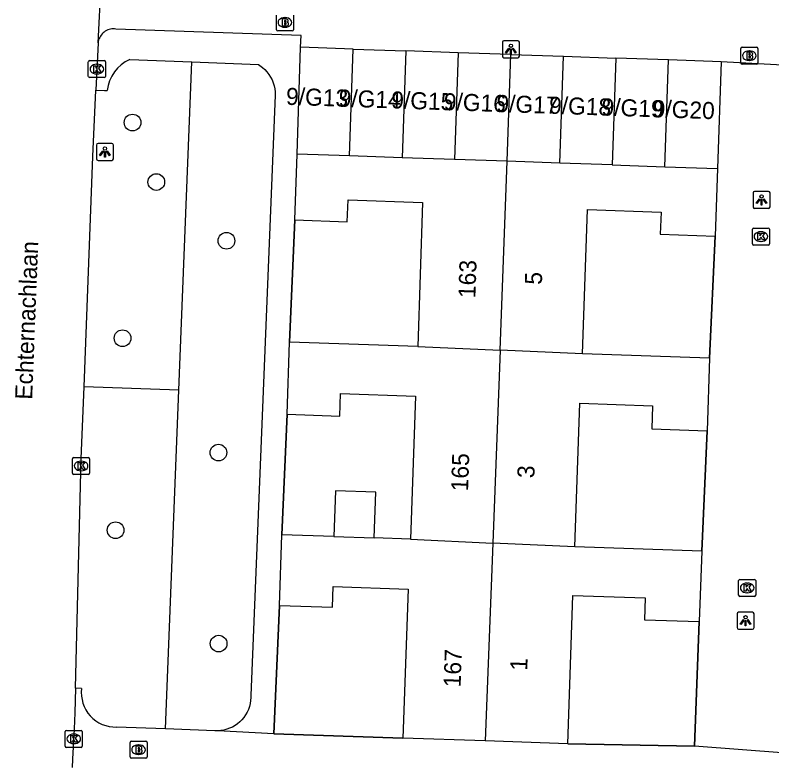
# Model space of a CAD drawing. Extents: x 160787 to 161428, y 386828 to 387483.
# Drawn here: x 160937.91 to 160982.31, y 387304.46 to 387348.48 of the extents above; entities that cross this region are included whole.
import ezdxf

# ---------------------------------------------------------------- set-up
doc = ezdxf.new("R2010")
doc.units = 0
for name, color, linetype in [('IMGEO_Boom', 7, 'Continuous'), ('IMGEO_Brandkraan', 7, 'Continuous'), ('IMGEO_Groenvoorziening', 7, 'Continuous'), ('IMGEO_Kolk', 7, 'Continuous'), ('IMGEO_Lichtpunt', 7, 'Continuous'), ('IMGEO_Muur', 7, 'Continuous'), ('IMGEO_Openbare_ruimte_label', 7, 'Continuous'), ('IMGEO_Pand', 7, 'Continuous'), ('IMGEO_Pand_nummerreeks', 7, 'Continuous'), ('IMGEO_Rijbaan_lokaal_gesloten', 7, 'Continuous'), ('IMGEO_Rijbaan_lokaal_open', 7, 'Continuous'), ('IMGEO_Voetpad_open', 7, 'Continuous')]:
    doc.layers.add(name, color=color, linetype=linetype)

msp = doc.modelspace()

# ---------------------------------------------------------------- linework, layer by layer
at = {"layer": 'IMGEO_Boom'}
for centre in [(160944.795, 387342.186), (160946.193, 387338.697), (160950.31, 387335.252), (160944.21, 387329.535), (160949.837, 387322.826), (160943.805, 387318.279), (160949.851, 387311.625)]:
    msp.add_circle(centre, 0.489, dxfattribs=at)
at = {"layer": 'IMGEO_Brandkraan'}
for p, q in [((160953.239, 387347.631), (160953.239, 387348.483)), ((160954.24, 387348.483), (160954.24, 387347.631)), ((160953.727, 387348.337), (160953.752, 387348.337)), ((160954.166, 387347.557), (160953.314, 387347.557)), ((160953.75, 387347.777), (160953.725, 387347.777)), ((160980.488, 387345.681), (160980.488, 387346.533)), ((160980.563, 387346.607), (160981.415, 387346.607)), ((160980.976, 387346.387), (160981.001, 387346.387)), ((160981.489, 387346.533), (160981.489, 387345.681)), ((160980.999, 387345.827), (160980.974, 387345.827)), ((160981.415, 387345.607), (160980.563, 387345.607)), ((160944.651, 387304.979), (160944.651, 387305.831)), ((160944.726, 387305.905), (160945.578, 387305.905)), ((160945.652, 387305.831), (160945.652, 387304.979)), ((160945.139, 387305.685), (160945.164, 387305.685)), ((160945.578, 387304.905), (160944.726, 387304.905)), ((160945.162, 387305.125), (160945.137, 387305.125))]:
    msp.add_line(p, q, dxfattribs=at)
for points in [[(160953.239, 387347.631), (160953.239, 387348.483)], [(160954.24, 387348.483), (160954.24, 387347.631)], [(160953.587, 387348.257), (160953.587, 387347.857), (160953.8, 387347.857)], [(160953.818, 387348.257), (160953.587, 387348.257)], [(160953.766, 387348.176), (160953.712, 387348.176), (160953.712, 387348.1)], [(160953.712, 387348.1), (160953.765, 387348.1)], [(160953.774, 387348.024), (160953.712, 387348.024), (160953.712, 387347.943)], [(160954.166, 387347.557), (160953.314, 387347.557)], [(160953.712, 387347.943), (160953.774, 387347.943)], [(160980.488, 387345.681), (160980.488, 387346.533)], [(160980.563, 387346.607), (160981.415, 387346.607)], [(160980.836, 387346.307), (160980.836, 387345.907), (160981.049, 387345.907)], [(160981.067, 387346.307), (160980.836, 387346.307)], [(160981.015, 387346.226), (160980.961, 387346.226), (160980.961, 387346.15)], [(160981.489, 387346.533), (160981.489, 387345.681)], [(160980.961, 387346.15), (160981.014, 387346.15)], [(160981.023, 387346.074), (160980.961, 387346.074), (160980.961, 387345.993)], [(160980.961, 387345.993), (160981.023, 387345.993)], [(160981.415, 387345.607), (160980.563, 387345.607)], [(160944.651, 387304.979), (160944.651, 387305.831)], [(160944.726, 387305.905), (160945.578, 387305.905)], [(160945.652, 387305.831), (160945.652, 387304.979)], [(160944.999, 387305.605), (160944.999, 387305.205), (160945.212, 387305.205)], [(160945.23, 387305.605), (160944.999, 387305.605)], [(160945.178, 387305.524), (160945.124, 387305.524), (160945.124, 387305.448)], [(160945.124, 387305.448), (160945.177, 387305.448)], [(160945.186, 387305.372), (160945.124, 387305.372), (160945.124, 387305.291)], [(160945.578, 387304.905), (160944.726, 387304.905)], [(160945.124, 387305.291), (160945.186, 387305.291)]]:
    msp.add_lwpolyline(points, dxfattribs=at)
for centre, radius, start, end in [((160953.767, 387348.138), 0.0379, 267.8285, 90.9355), ((160953.775, 387347.983), 0.0404, 269.8759, 90.5077), ((160953.822, 387348.112), 0.145, 59.4692, 91.5367), ((160953.847, 387348.159), 0.0922, 285.5137, 58.1501), ((160953.852, 387347.967), 0.105, 301.3115, 78.989), ((160953.316, 387347.633), 0.0765, 181.552, 268.448), ((160953.316, 387347.633), 0.0765, 181.552, 268.448), ((160953.806, 387348.108), 0.251, 268.6676, 293.5347), ((160954.164, 387347.633), 0.0765, 271.552, 358.448), ((160954.164, 387347.633), 0.0765, 271.552, 358.448), ((160980.565, 387346.531), 0.0765, 91.552, 178.448), ((160980.565, 387346.531), 0.0765, 91.552, 178.448), ((160981.016, 387346.188), 0.0379, 267.8285, 90.9355), ((160981.071, 387346.162), 0.145, 59.4692, 91.5367), ((160981.096, 387346.209), 0.0922, 285.5137, 58.1501), ((160981.413, 387346.531), 0.0765, 1.552, 88.448), ((160981.413, 387346.531), 0.0765, 1.552, 88.448), ((160981.024, 387346.033), 0.0404, 269.8759, 90.5077), ((160981.055, 387346.158), 0.251, 268.6676, 293.5347), ((160981.101, 387346.017), 0.105, 301.3115, 78.989), ((160980.565, 387345.683), 0.0765, 181.552, 268.448), ((160980.565, 387345.683), 0.0765, 181.552, 268.448), ((160981.413, 387345.683), 0.0765, 271.552, 358.448), ((160981.413, 387345.683), 0.0765, 271.552, 358.448), ((160944.728, 387305.829), 0.0765, 91.552, 178.448), ((160944.728, 387305.829), 0.0765, 91.552, 178.448), ((160945.576, 387305.829), 0.0765, 1.552, 88.448), ((160945.576, 387305.829), 0.0765, 1.552, 88.448), ((160945.179, 387305.486), 0.0379, 267.8285, 90.9355), ((160945.187, 387305.331), 0.0404, 269.8759, 90.5077), ((160945.234, 387305.46), 0.145, 59.4692, 91.5367), ((160945.259, 387305.507), 0.0922, 285.5137, 58.1501), ((160945.264, 387305.315), 0.105, 301.3115, 78.989), ((160944.728, 387304.981), 0.0765, 181.552, 268.448), ((160944.728, 387304.981), 0.0765, 181.552, 268.448), ((160945.218, 387305.456), 0.251, 268.6676, 293.5347), ((160945.576, 387304.981), 0.0765, 271.552, 358.448), ((160945.576, 387304.981), 0.0765, 271.552, 358.448)]:
    msp.add_arc(centre, radius, start, end, dxfattribs=at)
for centre, major_axis, ratio, start_param, end_param in [((160953.726, 387348.057), (-0.387, 0.002), 0.722429, 4.712389, 7.853982), ((160953.751, 387348.057), (-0.39, 0.002), 0.717154, 1.570796, 4.712389), ((160980.975, 387346.107), (-0.387, 0.002), 0.722429, 4.712389, 7.853982), ((160981, 387346.107), (-0.39, 0.002), 0.717154, 1.570796, 4.712389), ((160945.138, 387305.405), (-0.387, 0.002), 0.722429, 4.712389, 7.853982), ((160945.163, 387305.405), (-0.39, 0.002), 0.717154, 1.570796, 4.712389)]:
    msp.add_ellipse(centre, major_axis=major_axis, ratio=ratio, start_param=start_param, end_param=end_param, dxfattribs=at)
at = {"layer": 'IMGEO_Groenvoorziening'}
for points in [[(160947.517, 387326.494), (160948.269, 387345.743)], [(160947.517, 387326.494), (160941.952, 387326.681)], [(160946.741, 387306.626), (160947.517, 387326.494)]]:
    msp.add_lwpolyline(points, dxfattribs=at)
at = {"layer": 'IMGEO_Kolk'}
for p, q in [((160942.278, 387345.82), (160943.13, 387345.82)), ((160942.203, 387344.894), (160942.203, 387345.746)), ((160942.691, 387345.6), (160942.716, 387345.6)), ((160943.204, 387345.746), (160943.204, 387344.894)), ((160942.714, 387345.04), (160942.689, 387345.04)), ((160943.13, 387344.82), (160942.278, 387344.82)), ((160981.244, 387335.997), (160982.096, 387335.997)), ((160981.169, 387335.071), (160981.169, 387335.923)), ((160981.657, 387335.777), (160981.682, 387335.777)), ((160982.17, 387335.923), (160982.17, 387335.071)), ((160981.68, 387335.217), (160981.655, 387335.217)), ((160982.096, 387334.997), (160981.244, 387334.997)), ((160941.278, 387321.619), (160941.278, 387322.471)), ((160941.353, 387322.545), (160942.205, 387322.545)), ((160941.766, 387322.325), (160941.791, 387322.325)), ((160942.279, 387322.471), (160942.279, 387321.619)), ((160942.205, 387321.545), (160941.353, 387321.545)), ((160941.789, 387321.765), (160941.764, 387321.765)), ((160980.364, 387314.467), (160980.364, 387315.319)), ((160980.439, 387315.393), (160981.291, 387315.393)), ((160980.852, 387315.173), (160980.877, 387315.173)), ((160981.365, 387315.319), (160981.365, 387314.467)), ((160981.291, 387314.393), (160980.439, 387314.393)), ((160980.875, 387314.613), (160980.85, 387314.613)), ((160940.846, 387305.614), (160940.846, 387306.466)), ((160940.921, 387306.54), (160941.773, 387306.54)), ((160941.334, 387306.32), (160941.359, 387306.32)), ((160941.847, 387306.466), (160941.847, 387305.614)), ((160941.773, 387305.54), (160940.921, 387305.54)), ((160941.357, 387305.76), (160941.332, 387305.76))]:
    msp.add_line(p, q, dxfattribs=at)
for points in [[(160942.278, 387345.82), (160943.13, 387345.82)], [(160942.203, 387344.894), (160942.203, 387345.746)], [(160942.524, 387345.52), (160942.647, 387345.52), (160942.647, 387345.369), (160942.777, 387345.52), (160942.941, 387345.52), (160942.795, 387345.369), (160942.948, 387345.12), (160942.796, 387345.12), (160942.711, 387345.284), (160942.647, 387345.217), (160942.647, 387345.12), (160942.524, 387345.12), (160942.524, 387345.52)], [(160943.204, 387345.746), (160943.204, 387344.894)], [(160943.13, 387344.82), (160942.278, 387344.82)], [(160981.244, 387335.997), (160982.096, 387335.997)], [(160981.169, 387335.071), (160981.169, 387335.923)], [(160981.49, 387335.697), (160981.613, 387335.697), (160981.613, 387335.546), (160981.743, 387335.697), (160981.907, 387335.697), (160981.761, 387335.546), (160981.914, 387335.297), (160981.762, 387335.297), (160981.677, 387335.461), (160981.613, 387335.394), (160981.613, 387335.297), (160981.49, 387335.297), (160981.49, 387335.697)], [(160982.17, 387335.923), (160982.17, 387335.071)], [(160982.096, 387334.997), (160981.244, 387334.997)], [(160941.278, 387321.619), (160941.278, 387322.471)], [(160941.353, 387322.545), (160942.205, 387322.545)], [(160941.599, 387322.245), (160941.722, 387322.245), (160941.722, 387322.094), (160941.852, 387322.245), (160942.016, 387322.245), (160941.87, 387322.094), (160942.023, 387321.845), (160941.871, 387321.845), (160941.786, 387322.009), (160941.722, 387321.942), (160941.722, 387321.845), (160941.599, 387321.845), (160941.599, 387322.245)], [(160942.279, 387322.471), (160942.279, 387321.619)], [(160942.205, 387321.545), (160941.353, 387321.545)], [(160980.364, 387314.467), (160980.364, 387315.319)], [(160980.439, 387315.393), (160981.291, 387315.393)], [(160981.365, 387315.319), (160981.365, 387314.467)], [(160980.685, 387315.093), (160980.808, 387315.093), (160980.808, 387314.942), (160980.938, 387315.093), (160981.102, 387315.093), (160980.956, 387314.942), (160981.109, 387314.693), (160980.957, 387314.693), (160980.872, 387314.857), (160980.808, 387314.79), (160980.808, 387314.693), (160980.685, 387314.693), (160980.685, 387315.093)], [(160981.291, 387314.393), (160980.439, 387314.393)], [(160940.846, 387305.614), (160940.846, 387306.466)], [(160940.921, 387306.54), (160941.773, 387306.54)], [(160941.167, 387306.24), (160941.29, 387306.24), (160941.29, 387306.089), (160941.42, 387306.24), (160941.584, 387306.24), (160941.438, 387306.089), (160941.591, 387305.84), (160941.439, 387305.84), (160941.354, 387306.004), (160941.29, 387305.937), (160941.29, 387305.84), (160941.167, 387305.84), (160941.167, 387306.24)], [(160941.847, 387306.466), (160941.847, 387305.614)], [(160941.773, 387305.54), (160940.921, 387305.54)]]:
    msp.add_lwpolyline(points, dxfattribs=at)
for centre, start, end in [((160942.28, 387345.744), 91.552, 178.448), ((160942.28, 387345.744), 91.552, 178.448), ((160943.128, 387345.744), 1.552, 88.448), ((160943.128, 387345.744), 1.552, 88.448), ((160942.28, 387344.896), 181.552, 268.448), ((160942.28, 387344.896), 181.552, 268.448), ((160943.128, 387344.896), 271.552, 358.448), ((160943.128, 387344.896), 271.552, 358.448), ((160981.246, 387335.921), 91.552, 178.448), ((160981.246, 387335.921), 91.552, 178.448), ((160982.094, 387335.921), 1.552, 88.448), ((160982.094, 387335.921), 1.552, 88.448), ((160981.246, 387335.073), 181.552, 268.448), ((160981.246, 387335.073), 181.552, 268.448), ((160982.094, 387335.073), 271.552, 358.448), ((160982.094, 387335.073), 271.552, 358.448), ((160941.355, 387322.469), 91.552, 178.448), ((160941.355, 387322.469), 91.552, 178.448), ((160942.203, 387322.469), 1.552, 88.448), ((160942.203, 387322.469), 1.552, 88.448), ((160941.355, 387321.621), 181.552, 268.448), ((160941.355, 387321.621), 181.552, 268.448), ((160942.203, 387321.621), 271.552, 358.448), ((160942.203, 387321.621), 271.552, 358.448), ((160980.441, 387315.317), 91.552, 178.448), ((160980.441, 387315.317), 91.552, 178.448), ((160981.289, 387315.317), 1.552, 88.448), ((160981.289, 387315.317), 1.552, 88.448), ((160980.441, 387314.469), 181.552, 268.448), ((160980.441, 387314.469), 181.552, 268.448), ((160981.289, 387314.469), 271.552, 358.448), ((160981.289, 387314.469), 271.552, 358.448), ((160940.923, 387306.464), 91.552, 178.448), ((160940.923, 387306.464), 91.552, 178.448), ((160941.771, 387306.464), 1.552, 88.448), ((160941.771, 387306.464), 1.552, 88.448), ((160940.923, 387305.616), 181.552, 268.448), ((160940.923, 387305.616), 181.552, 268.448), ((160941.771, 387305.616), 271.552, 358.448), ((160941.771, 387305.616), 271.552, 358.448)]:
    msp.add_arc(centre, 0.0765, start, end, dxfattribs=at)
for centre, major_axis, ratio, start_param, end_param in [((160942.69, 387345.32), (-0.387, 0.002), 0.722429, 4.712389, 7.853982), ((160942.715, 387345.32), (-0.39, 0.002), 0.717154, 1.570796, 4.712389), ((160981.656, 387335.497), (-0.387, 0.002), 0.722429, 4.712389, 7.853982), ((160981.681, 387335.497), (-0.39, 0.002), 0.717154, 1.570796, 4.712389), ((160941.765, 387322.045), (-0.387, 0.002), 0.722429, 4.712389, 7.853982), ((160941.79, 387322.045), (-0.39, 0.002), 0.717154, 1.570796, 4.712389), ((160980.851, 387314.893), (-0.387, 0.002), 0.722429, 4.712389, 7.853982), ((160980.876, 387314.893), (-0.39, 0.002), 0.717154, 1.570796, 4.712389), ((160941.333, 387306.04), (-0.387, 0.002), 0.722429, 4.712389, 7.853982), ((160941.358, 387306.04), (-0.39, 0.002), 0.717154, 1.570796, 4.712389)]:
    msp.add_ellipse(centre, major_axis=major_axis, ratio=ratio, start_param=start_param, end_param=end_param, dxfattribs=at)
at = {"layer": 'IMGEO_Lichtpunt'}
for p, q in [((160966.499, 387346.889), (160966.499, 387346.082)), ((160966.499, 387346.889), (160966.499, 387346.082)), ((160967.401, 387346.984), (160966.593, 387346.984)), ((160967.401, 387346.984), (160966.593, 387346.984)), ((160967.495, 387346.082), (160967.495, 387346.889)), ((160967.495, 387346.082), (160967.495, 387346.889)), ((160966.593, 387345.988), (160967.401, 387345.988)), ((160966.593, 387345.988), (160967.401, 387345.988)), ((160942.678, 387340.864), (160942.678, 387340.057)), ((160942.678, 387340.864), (160942.678, 387340.057)), ((160943.58, 387340.959), (160942.772, 387340.959)), ((160943.58, 387340.959), (160942.772, 387340.959)), ((160943.674, 387340.057), (160943.674, 387340.864)), ((160943.674, 387340.057), (160943.674, 387340.864)), ((160942.772, 387339.963), (160943.58, 387339.963)), ((160942.772, 387339.963), (160943.58, 387339.963)), ((160981.209, 387338.055), (160981.209, 387337.248)), ((160981.209, 387338.055), (160981.209, 387337.248)), ((160982.111, 387338.15), (160981.303, 387338.15)), ((160982.111, 387338.15), (160981.303, 387338.15)), ((160982.205, 387337.248), (160982.205, 387338.055)), ((160982.205, 387337.248), (160982.205, 387338.055)), ((160981.303, 387337.154), (160982.111, 387337.154)), ((160981.303, 387337.154), (160982.111, 387337.154)), ((160980.271, 387313.374), (160980.271, 387312.567)), ((160980.271, 387313.374), (160980.271, 387312.567)), ((160981.173, 387313.469), (160980.365, 387313.469)), ((160981.173, 387313.469), (160980.365, 387313.469)), ((160981.267, 387312.567), (160981.267, 387313.374)), ((160981.267, 387312.567), (160981.267, 387313.374)), ((160980.365, 387312.473), (160981.173, 387312.473)), ((160980.365, 387312.473), (160981.173, 387312.473))]:
    msp.add_line(p, q, dxfattribs=at)
for points in [[(160966.873, 387346.553), (160966.912, 387346.525), (160966.724, 387346.263), (160966.686, 387346.29), (160966.873, 387346.553)], [(160966.975, 387346.505), (160967.022, 387346.505), (160967.022, 387346.183), (160966.975, 387346.183), (160966.975, 387346.505)], [(160967.085, 387346.525), (160967.123, 387346.552), (160967.31, 387346.29), (160967.271, 387346.262), (160967.085, 387346.525)], [(160943.052, 387340.528), (160943.091, 387340.5), (160942.903, 387340.238), (160942.865, 387340.265), (160943.052, 387340.528)], [(160943.154, 387340.48), (160943.201, 387340.48), (160943.201, 387340.158), (160943.154, 387340.158), (160943.154, 387340.48)], [(160943.264, 387340.5), (160943.302, 387340.527), (160943.489, 387340.265), (160943.45, 387340.237), (160943.264, 387340.5)], [(160981.583, 387337.719), (160981.622, 387337.691), (160981.434, 387337.429), (160981.396, 387337.456), (160981.583, 387337.719)], [(160981.685, 387337.671), (160981.732, 387337.671), (160981.732, 387337.349), (160981.685, 387337.349), (160981.685, 387337.671)], [(160981.795, 387337.691), (160981.833, 387337.718), (160982.02, 387337.456), (160981.981, 387337.428), (160981.795, 387337.691)], [(160980.645, 387313.038), (160980.684, 387313.01), (160980.496, 387312.748), (160980.458, 387312.775), (160980.645, 387313.038)], [(160980.747, 387312.99), (160980.794, 387312.99), (160980.794, 387312.668), (160980.747, 387312.668), (160980.747, 387312.99)], [(160980.857, 387313.01), (160980.895, 387313.037), (160981.082, 387312.775), (160981.043, 387312.747), (160980.857, 387313.01)]]:
    msp.add_lwpolyline(points, dxfattribs=at)
for centre in [(160966.998, 387346.687), (160943.177, 387340.662), (160981.708, 387337.853), (160980.77, 387313.172)]:
    msp.add_circle(centre, 0.0994, dxfattribs=at)
for centre, start, end in [((160966.593, 387346.889), 90, 180), ((160966.593, 387346.889), 90, 180), ((160967.401, 387346.889), 0, 90), ((160967.401, 387346.889), 0, 90), ((160966.593, 387346.082), 180, 270), ((160966.593, 387346.082), 180, 270), ((160967.401, 387346.082), 270, 0), ((160967.401, 387346.082), 270, 360), ((160942.772, 387340.864), 90, 180), ((160942.772, 387340.864), 90, 180), ((160943.58, 387340.864), 0, 90), ((160943.58, 387340.864), 0, 90), ((160942.772, 387340.057), 180, 270), ((160942.772, 387340.057), 180, 270), ((160943.58, 387340.057), 270, 0), ((160943.58, 387340.057), 270, 360), ((160981.303, 387338.055), 90, 180), ((160981.303, 387338.055), 90, 180), ((160982.111, 387338.055), 0, 90), ((160982.111, 387338.055), 0, 90), ((160981.303, 387337.248), 180, 270), ((160981.303, 387337.248), 180, 270), ((160982.111, 387337.248), 270, 0), ((160982.111, 387337.248), 270, 360), ((160980.365, 387313.374), 90, 180), ((160980.365, 387313.374), 90, 180), ((160981.173, 387313.374), 0, 90), ((160981.173, 387313.374), 0, 90), ((160980.365, 387312.567), 180, 270), ((160980.365, 387312.567), 180, 270), ((160981.173, 387312.567), 270, 0), ((160981.173, 387312.567), 270, 360)]:
    msp.add_arc(centre, 0.0946, start, end, dxfattribs=at)
at = {"layer": 'IMGEO_Muur'}
for points in [[(160954.318, 387336.476), (160954.012, 387329.308)], [(160978.655, 387328.372), (160978.983, 387335.52)], [(160953.868, 387325.079), (160953.561, 387318.014)], [(160978.196, 387317.046), (160978.51, 387324.111)], [(160953.419, 387313.867), (160953.082, 387306.333)], [(160970.332, 387305.758), (160977.765, 387305.618), (160978.055, 387312.917)], [(160953.082, 387306.333), (160960.665, 387306.088)]]:
    msp.add_lwpolyline(points, dxfattribs=at)
at = {"layer": 'IMGEO_Pand'}
for points in [[(160954.449, 387340.332), (160954.663, 387346.596)], [(160957.747, 387346.491), (160954.663, 387346.596)], [(160957.533, 387340.227), (160957.747, 387346.491)], [(160957.747, 387346.491), (160960.83, 387346.386)], [(160960.83, 387346.386), (160960.617, 387340.122)], [(160963.914, 387346.28), (160960.83, 387346.386)], [(160963.914, 387346.28), (160963.7, 387340.017)], [(160966.998, 387346.175), (160963.914, 387346.28)], [(160966.788, 387339.912), (160966.998, 387346.175)], [(160966.998, 387346.175), (160970.082, 387346.07)], [(160969.868, 387339.807), (160970.082, 387346.07)], [(160970.082, 387346.07), (160973.166, 387345.964)], [(160973.166, 387345.964), (160972.952, 387339.702)], [(160976.249, 387345.859), (160973.166, 387345.964)], [(160976.036, 387339.597), (160976.249, 387345.859)], [(160979.333, 387345.754), (160976.249, 387345.859)], [(160979.333, 387345.754), (160979.119, 387339.492)], [(160954.318, 387336.476), (160954.449, 387340.332)], [(160957.533, 387340.227), (160954.449, 387340.332)], [(160960.617, 387340.122), (160957.533, 387340.227)], [(160963.7, 387340.017), (160960.617, 387340.122)], [(160966.788, 387339.912), (160963.7, 387340.017)], [(160966.368, 387328.837), (160966.788, 387339.912)], [(160969.868, 387339.807), (160966.788, 387339.912)], [(160972.952, 387339.702), (160969.868, 387339.807)], [(160972.952, 387339.702), (160976.036, 387339.597)], [(160976.036, 387339.597), (160979.119, 387339.492)], [(160979.119, 387339.492), (160978.983, 387335.52)], [(160954.318, 387336.476), (160957.399, 387336.371), (160957.443, 387337.649), (160961.822, 387337.499), (160961.534, 387329.052)], [(160971.199, 387328.627), (160971.488, 387337.077), (160975.81, 387336.929), (160975.766, 387335.63), (160978.983, 387335.52)], [(160953.868, 387325.079), (160954.012, 387329.308)], [(160961.534, 387329.052), (160954.012, 387329.308)], [(160961.534, 387329.052), (160966.368, 387328.837)], [(160966.368, 387328.837), (160965.938, 387317.527)], [(160971.199, 387328.627), (160966.368, 387328.837)], [(160978.655, 387328.372), (160971.199, 387328.627)], [(160978.655, 387328.372), (160978.51, 387324.111)], [(160953.868, 387325.079), (160956.965, 387324.973), (160957.01, 387326.285), (160961.393, 387326.136), (160961.107, 387317.756)], [(160970.758, 387317.3), (160971.045, 387325.718), (160975.313, 387325.572), (160975.267, 387324.221), (160978.51, 387324.111)], [(160958.978, 387317.829), (160959.069, 387320.509), (160956.708, 387320.589), (160956.617, 387317.91)], [(160953.419, 387313.867), (160953.561, 387318.014)], [(160956.617, 387317.91), (160953.561, 387318.014)], [(160956.617, 387317.91), (160958.978, 387317.829)], [(160961.107, 387317.756), (160958.978, 387317.829)], [(160961.107, 387317.756), (160965.938, 387317.527)], [(160965.938, 387317.527), (160965.498, 387305.923)], [(160970.758, 387317.3), (160965.938, 387317.527)], [(160978.196, 387317.046), (160970.758, 387317.3)], [(160978.196, 387317.046), (160978.055, 387312.917)], [(160953.419, 387313.867), (160956.539, 387313.76), (160956.58, 387314.968), (160960.963, 387314.818), (160960.665, 387306.088)], [(160970.332, 387305.758), (160970.629, 387314.454), (160974.888, 387314.309), (160974.844, 387313.027), (160978.055, 387312.917)], [(160965.498, 387305.923), (160960.665, 387306.088)], [(160970.332, 387305.758), (160965.498, 387305.923)]]:
    msp.add_lwpolyline(points, dxfattribs=at)
at = {"layer": 'IMGEO_Rijbaan_lokaal_gesloten'}
for points in [[(160942.774, 387346.851), (160943.123, 387353.842)], [(160942.774, 387346.851), (160942.646, 387344.093)], [(160941.952, 387326.681), (160942.465, 387340.198), (160942.646, 387344.093)], [(160941.456, 387309.006), (160941.792, 387322.475), (160941.952, 387326.681)], [(160941.456, 387309.006), (160941.42, 387307.575), (160941.373, 387306.627), (160941.283, 387304.841), (160941.264, 387304.352)]]:
    msp.add_lwpolyline(points, dxfattribs=at)
at = {"layer": 'IMGEO_Rijbaan_lokaal_open'}
for points in [[(160954.663, 387346.596), (160954.685, 387347.288), (160943.825, 387347.669), (160943.744, 387347.678), (160943.662, 387347.679), (160943.58, 387347.673), (160943.499, 387347.66), (160943.42, 387347.64), (160943.342, 387347.613), (160943.268, 387347.578), (160943.197, 387347.538), (160943.129, 387347.491), (160943.067, 387347.438), (160943.009, 387347.38), (160942.956, 387347.317), (160942.91, 387347.25), (160942.869, 387347.178), (160942.835, 387347.104), (160942.808, 387347.026), (160942.788, 387346.947), (160942.776, 387346.866), (160942.774, 387346.851)], [(160984.758, 387345.458), (160979.333, 387345.754)]]:
    msp.add_lwpolyline(points, dxfattribs=at)
at = {"layer": 'IMGEO_Voetpad_open'}
for points in [[(160944.635, 387345.884), (160948.269, 387345.743)], [(160948.269, 387345.743), (160952.187, 387345.591), (160952.274, 387345.526), (160952.422, 387345.415), (160952.559, 387345.292), (160952.684, 387345.156), (160952.797, 387345.01), (160952.897, 387344.854), (160952.982, 387344.69), (160953.052, 387344.519), (160953.107, 387344.343), (160953.146, 387344.162), (160953.168, 387343.979), (160953.174, 387343.794), (160951.739, 387308.588), (160951.74, 387308.463), (160951.728, 387308.285), (160951.7, 387308.109), (160951.656, 387307.936), (160951.597, 387307.767), (160951.523, 387307.605), (160951.435, 387307.449), (160951.334, 387307.303), (160951.22, 387307.165), (160951.094, 387307.039), (160950.957, 387306.924), (160950.81, 387306.822), (160950.655, 387306.734), (160950.493, 387306.66), (160950.325, 387306.6), (160950.152, 387306.556), (160949.975, 387306.527), (160949.797, 387306.515)], [(160942.646, 387344.093), (160943.156, 387344.069), (160943.313, 387344.062)], [(160954.012, 387329.308), (160954.318, 387336.476)], [(160978.983, 387335.52), (160978.655, 387328.372)], [(160953.561, 387318.014), (160953.868, 387325.079)], [(160978.51, 387324.111), (160978.196, 387317.046)], [(160953.082, 387306.333), (160953.419, 387313.867)], [(160978.055, 387312.917), (160977.765, 387305.618)], [(160941.806, 387308.988), (160941.456, 387309.006)], [(160946.741, 387306.626), (160943.863, 387306.734)], [(160949.797, 387306.515), (160949.619, 387306.518), (160946.741, 387306.626)], [(160953.082, 387306.333), (160949.797, 387306.515)], [(160960.665, 387306.088), (160953.082, 387306.333)], [(160977.765, 387305.618), (160970.332, 387305.758)], [(160983.144, 387305.21), (160977.765, 387305.618)]]:
    msp.add_lwpolyline(points, dxfattribs=at)
for centre, radius, start, end in [((160945.559, 387343.823), 2.259, 114.1548, 173.9177), ((160943.801, 387308.743), 2.01, 172.9896, 271.7775)]:
    msp.add_arc(centre, radius, start, end, dxfattribs=at)

# ---------------------------------------------------------------- texts
at = {"layer": 'IMGEO_Openbare_ruimte_label'}
msp.add_text('Echternachlaan', height=1, rotation=87.7644, dxfattribs=at).set_placement((160938.903, 387325.921))
at = {"layer": 'IMGEO_Pand_nummerreeks'}
for s, rotation, p in [('9/G13', 358.0667, (160953.793, 387343.227)), ('9/G14', 358.0667, (160956.879, 387343.123)), ('9/G15', 358.0667, (160959.965, 387343.018)), ('9/G16', 358.0667, (160963.051, 387342.914)), ('9/G17', 358.0667, (160966.137, 387342.81)), ('9/G18', 358.0667, (160969.226, 387342.706)), ('9/G19', 358.0667, (160972.305, 387342.602)), ('9/G20', 358.0667, (160975.306, 387342.501)), ('163', 88.0473, (160964.912, 387331.878)), ('5', 88.0412, (160968.816, 387332.662)), ('165', 88.0453, (160964.484, 387320.548)), ('3', 88.0473, (160968.374, 387321.319)), ('167', 88.0464, (160964.048, 387309.054)), ('1', 88.0439, (160967.957, 387310.03))]:
    msp.add_text(s, height=1, rotation=rotation, dxfattribs=at).set_placement(p)

doc.saveas('drawing.dxf')
